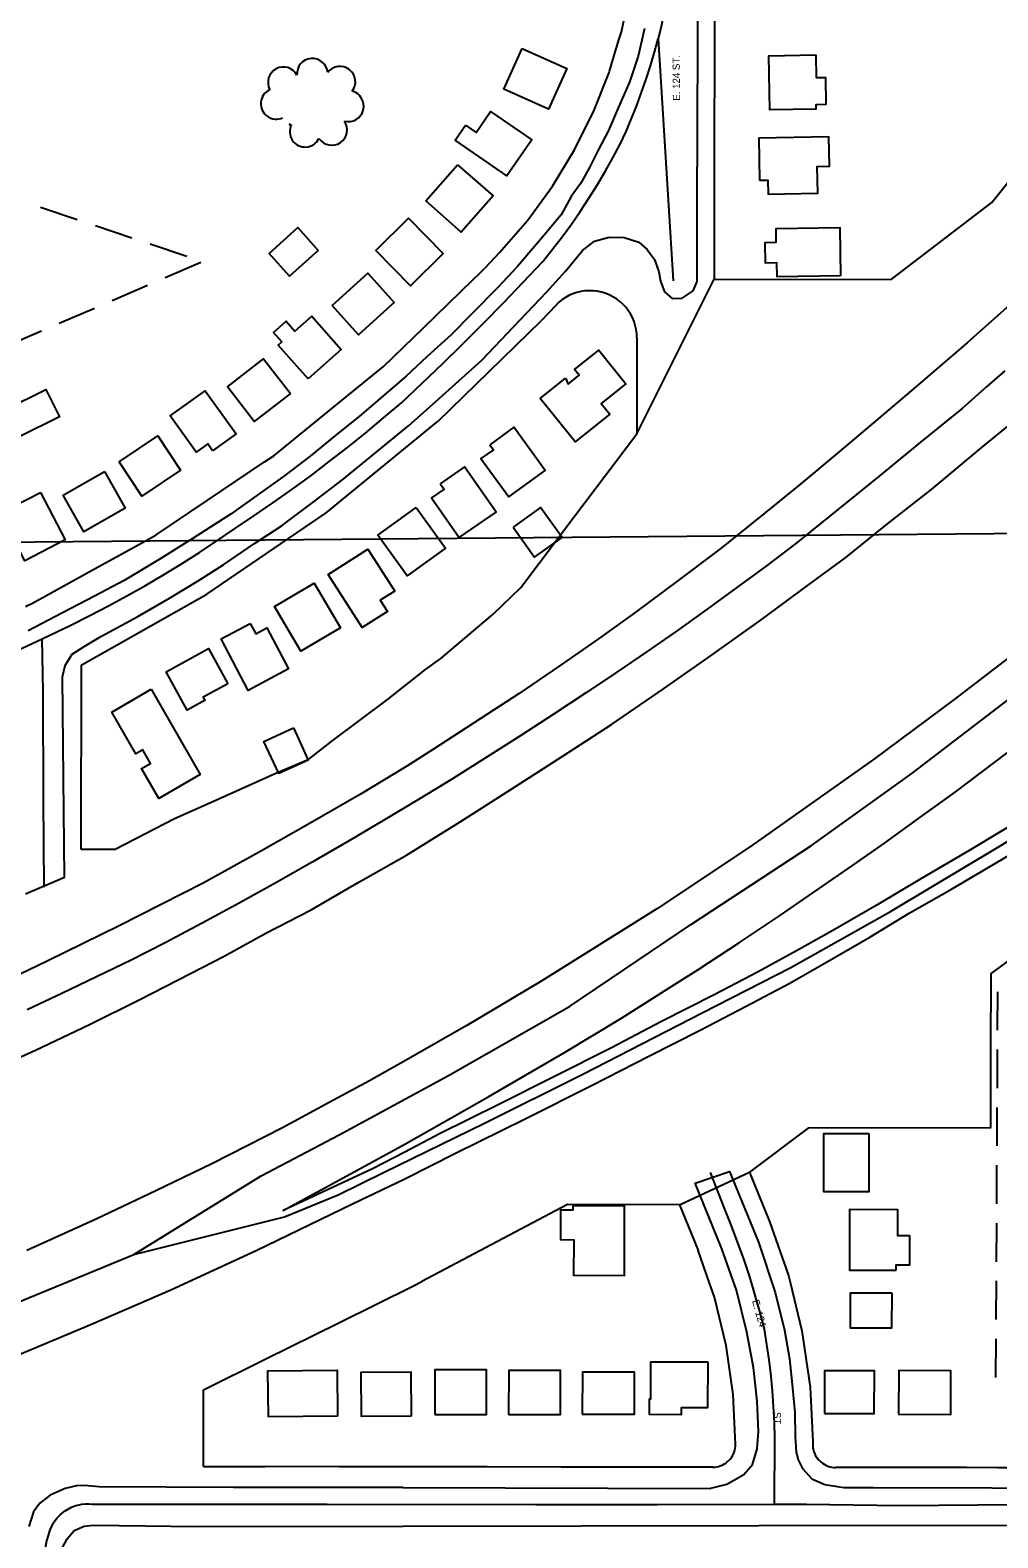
# Model space of a CAD drawing. Extents: x -2233 to 187241, y 4582 to 150524.
# Drawn here: x 112255 to 112882, y 58418 to 59395 of the extents above; entities that cross this region are included whole.
import ezdxf

# ---------------------------------------------------------------- set-up
doc = ezdxf.new("R2010")
doc.units = 0
for name, color, linetype in [('AP_X_Lights', 7, 'Continuous'), ('BLDG', 7, 'Continuous'), ('GE_X_CL_2000', 7, 'Continuous'), ('GRID', 7, 'Continuous'), ('INTERSTATE', 7, 'Continuous'), ('RECREATION', 7, 'Continuous'), ('ROAD', 7, 'Continuous'), ('ROAD-NAME', 7, 'Continuous'), ('RW_X_Fee_RW', 7, 'Continuous'), ('TREES', 7, 'Continuous')]:
    doc.layers.add(name, color=color, linetype=linetype)

msp = doc.modelspace()

# ---------------------------------------------------------------- linework, layer by layer
at = {"layer": 'AP_X_Lights'}
msp.add_line((112661.94, 59389.66), (112671.77, 59232.78), dxfattribs=at)
at = {"layer": 'BLDG'}
for points in [[(112573.74, 59383.4), (112602.84, 59370.37), (112591, 59343.92), (112561.9, 59356.94)], [(112764.24, 59379.14), (112764.47, 59364.52), (112770.44, 59364.62), (112770.73, 59346.95), (112764.22, 59346.85), (112764.26, 59343.96), (112734.41, 59343.47), (112733.83, 59378.64)], [(112537.18, 59333.66), (112543.96, 59328.98), (112553.35, 59342.59), (112580.01, 59324.19), (112563.86, 59300.8), (112530.42, 59323.87)], [(112727.81, 59297.97), (112733.12, 59298.05), (112733.27, 59289), (112765.47, 59289.53), (112765.18, 59306.94), (112773.03, 59307.07), (112772.72, 59325.99), (112727.37, 59325.25)], [(112531.95, 59307.97), (112554.93, 59287.73), (112534.32, 59264.33), (112511.34, 59284.57)], [(112522.68, 59250.55), (112501.36, 59229.56), (112478.88, 59252.4), (112500.19, 59273.38)], [(112441.58, 59252.48), (112422.96, 59235.79), (112409.73, 59250.54), (112428.36, 59267.23)], [(112780.33, 59235.98), (112739.07, 59235.3), (112738.92, 59244.32), (112731.63, 59244.2), (112731.42, 59257.61), (112738.62, 59257.73), (112738.48, 59266.59), (112779.8, 59267.27)], [(112490.83, 59218.62), (112467.62, 59197.83), (112450.61, 59216.84), (112473.82, 59237.62)], [(112434.98, 59169.31), (112415.66, 59191.13), (112417.94, 59193.14), (112412.49, 59199.29), (112420.71, 59206.56), (112426.51, 59200.03), (112437.48, 59209.74), (112456.45, 59188.32)], [(112423.51, 59159.75), (112400.02, 59141.64), (112382.7, 59164.12), (112406.19, 59182.23)], [(112601.84, 59169.59), (112603.76, 59165.85), (112610.83, 59171.51), (112607.79, 59175.32), (112623.44, 59187.85), (112640.94, 59166), (112625.11, 59153.33), (112630.64, 59146.42), (112608.16, 59128.41), (112585.59, 59156.58)], [(112238.79, 59149.35), (112264.96, 59162.32), (112273.73, 59144.62), (112247.58, 59131.64)], [(112373.08, 59122.64), (112369.93, 59127.04), (112362.45, 59121.68), (112345.56, 59145.27), (112368.25, 59161.51), (112388.29, 59133.53)], [(112312.42, 59115.43), (112337.6, 59132.18), (112352.38, 59109.95), (112327.21, 59093.2)], [(112552.8, 59126.54), (112555.16, 59123.3), (112547.12, 59117.48), (112565.1, 59092.65), (112588.71, 59109.74), (112568.39, 59137.82)], [(112520.71, 59101.22), (112523.17, 59097.68), (112515.14, 59092.12), (112533.06, 59066.28), (112556.89, 59082.79), (112536.52, 59112.17)], [(112302.95, 59109.19), (112316.46, 59085.43), (112289.64, 59070.16), (112276.12, 59093.92)], [(112261.56, 59095.62), (112277.48, 59064.81), (112251.27, 59051.26), (112235.34, 59082.07)], [(112505.11, 59085.76), (112524.09, 59059.5), (112499.23, 59041.52), (112480.24, 59067.79)], [(112567.93, 59073), (112581.9, 59053.59), (112599.69, 59066.4), (112585.72, 59085.81)], [(112491.22, 59031.7), (112481.82, 59025.66), (112486.43, 59018.49), (112470.05, 59007.95), (112447.93, 59042.31), (112473.71, 59058.9)], [(112456, 59007.86), (112430.27, 58992.72), (112413.25, 59021.63), (112438.98, 59036.77)], [(112397.51, 59010.72), (112401.12, 59003.92), (112408.31, 59007.73), (112422.41, 58981.15), (112396.25, 58967.28), (112378.55, 59000.67)], [(112382.89, 58971.6), (112367.08, 58962.89), (112368.18, 58960.89), (112356.69, 58954.55), (112343.05, 58979.3), (112370.35, 58994.34)], [(112333.31, 58967.99), (112365.12, 58912.77), (112338.24, 58897.27), (112327.08, 58916.64), (112332.9, 58919.99), (112327.88, 58928.68), (112323.38, 58926.1), (112307.74, 58953.26)], [(112425.47, 58942.99), (112435.08, 58922.12), (112416.01, 58913.33), (112406.4, 58934.2)], [(112798.68, 58680.06), (112798.59, 58642.17), (112769.34, 58642.24), (112769.43, 58680.13)], [(112606.74, 58633.29), (112606.73, 58630.43), (112598.62, 58630.45), (112598.58, 58611.27), (112607.26, 58611.25), (112607.2, 58588.16), (112640.18, 58588.09), (112640.28, 58633.21)], [(112816.37, 58591.42), (112816.39, 58595.05), (112825.19, 58595.04), (112825.23, 58613.65), (112817.39, 58613.67), (112817.43, 58630.67), (112786.12, 58630.74), (112786.03, 58591.5)], [(112813.43, 58576.79), (112813.38, 58553.93), (112786.72, 58553.99), (112786.77, 58576.86)], [(112454.03, 58496.84), (112409.25, 58496.45), (112408.99, 58526.22), (112453.77, 58526.61)], [(112517.2, 58498.01), (112550.7, 58497.93), (112550.77, 58526.8), (112517.26, 58526.88)], [(112565.05, 58497.95), (112598.69, 58497.86), (112598.76, 58526.49), (112565.12, 58526.57)], [(112694.15, 58532.09), (112694.08, 58502.27), (112677.03, 58502.31), (112677.01, 58497.82), (112656.35, 58497.87), (112656.38, 58508.05), (112657.17, 58508.05), (112657.23, 58532.17)], [(112769.86, 58498.58), (112802.15, 58498.51), (112802.22, 58526.25), (112769.93, 58526.33)], [(112817.91, 58498.08), (112851.82, 58498.01), (112851.88, 58526.3), (112817.97, 58526.38)], [(112501.8, 58496.94), (112469.7, 58496.66), (112469.45, 58525.4), (112501.54, 58525.68)], [(112612.79, 58498.18), (112646.6, 58498.11), (112646.66, 58525.3), (112612.85, 58525.38)]]:
    msp.add_lwpolyline(points, close=True, dxfattribs=at)
at = {"layer": 'GE_X_CL_2000'}
for points in [[(112674.75, 59513.68), (112673.38, 59479.04), (112672.72, 59467.46), (112671.83, 59455.9), (112670.73, 59444.36), (112669.4, 59432.84), (112667.86, 59421.35), (112666.1, 59409.89), (112664.12, 59398.47), (112661.94, 59389.66)], [(112322, 58601.64), (112419.7, 58625.98), (112454.58, 58640.34), (112483.87, 58654.7), (112549.39, 58686.78), (112613.25, 58718.64), (112690.58, 58758.24), (112748.04, 58787.66), (112812.69, 58824.06), (112883.1, 58866.13), (112968.12, 58917.71), (113054.39, 58971.65), (113150.57, 59034.21), (113253.76, 59104.14), (113362.87, 59177.68), (113450.77, 59237.58), (113520.19, 59286.04), (113597.75, 59341.18), (113697.89, 59412.19), (113699.46, 59413.32)], [(112262.59, 59000.74), (112281.2, 59009.65), (112293.44, 59015.77), (112305.57, 59022.1), (112317.59, 59028.63), (112329.51, 59035.36), (112341.3, 59042.29), (112352.98, 59049.42), (112364.53, 59056.75), (112375.95, 59064.27), (112387.25, 59071.98), (112399.8, 59080.32), (112412.23, 59088.84), (112424.53, 59097.56), (112436.7, 59106.46), (112448.73, 59115.54), (112460.63, 59124.8), (112472.39, 59134.25), (112484.01, 59143.87), (112495.49, 59153.66), (112508.98, 59166.34), (112522.34, 59179.16), (112535.57, 59192.12), (112548.68, 59205.2), (112561.66, 59218.43), (112574.51, 59231.78), (112587.23, 59245.26), (112593.58, 59253.17), (112599.75, 59261.23), (112605.73, 59269.43), (112611.52, 59277.76), (112617.12, 59286.23), (112622.51, 59294.83), (112627.7, 59303.55), (112632.69, 59312.39), (112637.47, 59321.34), (112641.2, 59329.62), (112644.73, 59337.99), (112648.08, 59346.43), (112651.24, 59354.95), (112654.21, 59363.53), (112656.98, 59372.18), (112659.56, 59380.89), (112661.94, 59389.66)], [(112886.89, 59174.51), (112875.07, 59164.21), (112859.18, 59150.01), (112832.21, 59128.11), (112805.23, 59106.22), (112778.24, 59084.34), (112751.25, 59062.47), (112732.26, 59048.11), (112713.13, 59033.93), (112693.87, 59019.94), (112674.47, 59006.14), (112654.94, 58992.53), (112635.27, 58979.1), (112615.48, 58965.87), (112593.97, 58951.61), (112572.33, 58937.55), (112550.56, 58923.68), (112528.67, 58910.01), (112506.65, 58896.55), (112484.51, 58883.28), (112461.13, 58869.49), (112437.63, 58855.91), (112414, 58842.53), (112390.26, 58829.37), (112366.41, 58816.41), (112342.44, 58803.67), (112320.2, 58792.51), (112297.86, 58781.54), (112275.44, 58770.76), (112252.92, 58760.16)], [(111689.35, 58856.66), (111717.85, 58861.84), (111813.36, 58878.53), (111930.32, 58899.31), (112008.92, 58912.76), (112091.39, 58932.64), (112118.84, 58941.41), (112135.86, 58947.46), (112152.8, 58953.73), (112169.65, 58960.22), (112186.42, 58966.94), (112203.1, 58973.87), (112219.68, 58981.01), (112236.17, 58988.37), (112262.59, 59000.74)], [(112263.92, 58839.7), (112263.46, 58896.5), (112263.3, 58966.44), (112262.59, 59000.74)], [(112322, 58601.64), (112404.65, 58652.72), (112455.09, 58679.29), (112526.13, 58717.6), (112604.53, 58762.37), (112683.68, 58815.8), (112761.41, 58866.74), (112826.6, 58913.46), (112889.1, 58961.39)], [(112695.63, 58654.76), (112705, 58631.03), (112709.4, 58620.19), (112713.56, 58609.25), (112717.48, 58598.22), (112721.14, 58587.11), (112724.56, 58575.93), (112727.73, 58564.67), (112730.65, 58553.34), (112732.34, 58543.35), (112733.78, 58533.33), (112734.8, 58524.82), (112735.94, 58513.19), (112736.66, 58503.1), (112737.14, 58492.99), (112737.37, 58482.87), (112737.31, 58439.82)], [(112186.48, 58545.96), (112322, 58601.64)], [(112269.58, 58427.26), (112272.33, 58431), (112273.94, 58432.68), (112275.69, 58434.21), (112277.56, 58435.58), (112281.63, 58437.81), (112283.8, 58438.65), (112288.31, 58439.74), (112290.62, 58439.99), (112292.94, 58440.04), (112295.26, 58439.88), (112345.06, 58439.79), (112447.33, 58439.8), (112582.73, 58439.67), (112661.55, 58439.69), (112737.31, 58439.82)], [(112737.31, 58439.82), (112758.26, 58439.86), (112818.97, 58438.91), (112894.08, 58439.53), (113038.93, 58438.62), (113119.5, 58438.41), (113160.7, 58439.44), (113241.06, 58439.03), (113306.38, 58438.54), (113333.66, 58438.38)], [(112269.58, 58427.26), (112267.53, 58423.1), (112266.39, 58419.6), (112265.46, 58416.05), (112264.74, 58412.44), (112264.24, 58408.8), (112263.96, 58405.13), (112263.64, 58395.93), (112263.24, 58319.73), (112263.59, 58276.24), (112262.77, 58209.88), (112262.61, 58127.98), (112262.43, 58100.01)]]:
    msp.add_lwpolyline(points, dxfattribs=at)
at = {"layer": 'GRID'}
msp.add_line((114999.62, 59087.27), (109999.81, 59043.63), dxfattribs=at)
at = {"layer": 'INTERSTATE'}
for points in [[(112907.51, 59232.8), (112862.27, 59192.62), (112826.07, 59161.49), (112804.67, 59143.36), (112779.53, 59122.13), (112754.84, 59101.33), (112731.68, 59082.48), (112702.78, 59059.57), (112674.98, 59038.51), (112646.23, 59017.15), (112623.3, 59000.74), (112597.79, 58982.99), (112571.97, 58965.32), (112542.33, 58946.09), (112516.27, 58929.11), (112499.04, 58918.1)], [(112498.75, 58860.45), (112533.71, 58882), (112566.55, 58903.11), (112599.85, 58924.51), (112631.7, 58945.26), (112665.57, 58968.27), (112695.81, 58989.36), (112728.88, 59013.07), (112758.64, 59035.1), (112783.6, 59053.47), (112809.72, 59074.31), (112839.5, 59097.78), (112873.46, 59125.95), (112902.62, 59149.86)], [(112899.26, 58996.17), (112853.92, 58961.28), (112801.6, 58922.4), (112758.95, 58892.18), (112721.84, 58866.05), (112661.22, 58825.69), (112586.49, 58778.97), (112537.95, 58750.16), (112498.1, 58727.36)], [(112497.84, 58673.17), (112552.22, 58704.05), (112601.25, 58732.53), (112638.3, 58754.88), (112668.5, 58774.15), (112687.81, 58786.21), (112714.75, 58803.81), (112740.69, 58821.22), (112765.82, 58838.47), (112788.68, 58854.21), (112808.84, 58868.31), (112833.1, 58886.01), (112854.65, 58901.39), (112888.38, 58926.78)], [(112499.04, 58918.1), (112469.44, 58900.23), (112436.35, 58881.2), (112404.88, 58863.28), (112366.89, 58842.37), (112312.56, 58814.58), (112265.79, 58791.79), (112225.73, 58772.49)], [(112903.33, 58887.36), (112864.15, 58863.63), (112832.34, 58845.19), (112803.36, 58827.88), (112775.32, 58811.55), (112751.82, 58798.51), (112726.75, 58784.8), (112698.75, 58770.21), (112663.65, 58752.45), (112631.68, 58735.57), (112594.33, 58716.84), (112558.74, 58698.84), (112520.19, 58679.88), (112497.81, 58667.94)], [(112497.72, 58650.6), (112530.69, 58667.38), (112575.38, 58689.34), (112619.14, 58711.44), (112656.3, 58730.48), (112689.27, 58747.1), (112719.15, 58762.71), (112746.92, 58777.37), (112771.24, 58791.15), (112799.28, 58807.35), (112824.68, 58822.79), (112852.27, 58838.44), (112881.25, 58855.44), (112912.88, 58874.32)], [(112226.05, 58719.57), (112258.18, 58734.18), (112293.3, 58750.77), (112325.89, 58766.89), (112358.74, 58783.7), (112380.61, 58795.06), (112407.66, 58809.95), (112437, 58825.1), (112467.59, 58842.72), (112498.75, 58860.45)], [(112498.1, 58727.36), (112474.82, 58714.27), (112448.6, 58700.14), (112418.35, 58683.72), (112372.65, 58660.4), (112336.37, 58642.83), (112297.98, 58624.84), (112252.71, 58604.31)], [(112497.81, 58667.94), (112476.72, 58657.27), (112418.91, 58630.17), (112462.52, 58653.9), (112497.84, 58673.17)], [(112246.69, 58536.34), (112294.62, 58556.58), (112346, 58578.85), (112401.37, 58604.35), (112463.91, 58634.48), (112497.72, 58650.6)]]:
    msp.add_lwpolyline(points, dxfattribs=at)
at = {"layer": 'RECREATION'}
for p, q in [((112261.58, 59280.53), (112285.28, 59272.57)), ((112297.13, 59268.59), (112320.83, 59260.64)), ((112332.68, 59256.65), (112356.38, 59248.7)), ((112365.36, 59244.59), (112342.4, 59234.69)), ((112330.92, 59229.74), (112307.97, 59219.84)), ((112296.49, 59214.89), (112273.54, 59204.99)), ((112262.06, 59200.04), (112239.11, 59190.14)), ((112882.14, 58746.99), (112882.26, 58772)), ((112881.95, 58709.49), (112882.07, 58734.49)), ((112881.76, 58672), (112881.88, 58696.99)), ((112881.58, 58634.49), (112881.7, 58659.5)), ((112881.4, 58596.99), (112881.52, 58621.99)), ((112881.2, 58559.5), (112881.33, 58584.49)), ((112881.02, 58522), (112881.14, 58547))]:
    msp.add_line(p, q, dxfattribs=at)
at = {"layer": 'ROAD'}
for points in [[(112500.11, 59138.77), (112517.86, 59154.58), (112547.69, 59181.33), (112572.54, 59207.49), (112589.58, 59225.44), (112601.82, 59239.05), (112612.95, 59252.43), (112620.76, 59258.52), (112630.27, 59260.98), (112639.91, 59260.81), (112649.57, 59257.78), (112654.84, 59253.03), (112659.72, 59246.65), (112662.38, 59238.52), (112663.58, 59232.47), (112666.2, 59225.57), (112671.05, 59221.38), (112677.59, 59221.46), (112684.76, 59226.19), (112687.23, 59232.25), (112687.29, 59279.98), (112687.96, 59440.44), (112687.05, 59496.28)], [(112653.13, 59396.37), (112648.96, 59378.38), (112643.36, 59361.42), (112636.25, 59345.39), (112629.84, 59330.09), (112623.17, 59317.41), (112617.53, 59306.29), (112611.91, 59296.05), (112605.62, 59287.41), (112599.02, 59275.54), (112588.09, 59262.3), (112570.77, 59242.12), (112557.93, 59228.19), (112541.3, 59211.5), (112527.76, 59197.84), (112512.25, 59183.78), (112498.54, 59170.89), (112486.39, 59160.33), (112468.45, 59144.97), (112451.88, 59131.74), (112436.27, 59119.02), (112420.03, 59106.56), (112404.84, 59095.84), (112385.08, 59081.73), (112359.84, 59065.42), (112338.51, 59052.09), (112315.73, 59038.59), (112296.61, 59028.46), (112275.83, 59017.46), (112253.46, 59005.92)], [(112251.69, 58835.37), (112276.97, 58846.29), (112276.03, 58953.39), (112275.84, 58976.08), (112277.55, 58983.41), (112282.11, 58990.74), (112289.85, 58995.75), (112300.55, 59002.22), (112324.53, 59015.13), (112345.25, 59027.07), (112363.76, 59038.36), (112380.41, 59048.98), (112400.35, 59062.4), (112417.46, 59073.83), (112438.31, 59089.39), (112457.44, 59103.96), (112477.67, 59120.42), (112498.04, 59136.94), (112500.11, 59138.77)], [(112496.75, 58450.57), (112695.36, 58450.03), (112706.61, 58452.77), (112717.61, 58459.06), (112723.27, 58465.63), (112726.24, 58475.78), (112726.98, 58486.91), (112726.14, 58506.65), (112723.77, 58528.41), (112719.49, 58551.33), (112712.85, 58578.52), (112703.29, 58605.39), (112686.08, 58647.94), (112708.31, 58655.4), (112727.01, 58609.59), (112737.86, 58577.1), (112744.03, 58552.53), (112747.2, 58534), (112748.77, 58519.65), (112750.53, 58499.33), (112750.83, 58483.58), (112751.41, 58473.61), (112752.81, 58468.48), (112755.64, 58462.9), (112761.57, 58456.26), (112770.16, 58452.63), (112782.51, 58450.73), (112801.56, 58450.6), (113185.45, 58449.62)], [(112496.75, 58450.57), (112386.7, 58450.61), (112299.64, 58451.12), (112292.1, 58451.62), (112285.71, 58451.86), (112277.5, 58449.97), (112267.86, 58445.56), (112261.06, 58440.42), (112256.97, 58434.85), (112254.02, 58425.33)], [(112495.06, 58107.73), (112295.51, 58109.44), (112283.79, 58109.95), (112277.77, 58113.54), (112275.12, 58117.76), (112273.48, 58122.29), (112273.31, 58134.84), (112273.51, 58195.99), (112274.59, 58351.42), (112275.21, 58404.37), (112275.33, 58410.97), (112278.86, 58417.44), (112283.44, 58422.75), (112289.77, 58425.55), (112295.73, 58426.21), (112362.83, 58425.35), (112496.62, 58425.47)], [(112496.62, 58425.47), (112842.72, 58426.13), (113141.4, 58425.35), (113294.22, 58425.62), (113306.3, 58422.73), (113313.33, 58418.51), (113317.46, 58412.71), (113319.98, 58407), (113320.73, 58399.9), (113321.3, 58389.12), (113319.34, 58112.68), (113316.76, 58107.43), (113313.28, 58104.31), (113307.39, 58101.92), (113293.07, 58101.55), (112776.79, 58106.01), (112495.06, 58107.73)]]:
    msp.add_lwpolyline(points, dxfattribs=at)
at = {"layer": 'RW_X_Fee_RW'}
for p, q in [((112813.17, 59233.58), (112878.34, 59283.49)), ((112559.18, 59251.06), (112549.85, 59241.15)), ((112648.15, 59133.63), (112698.27, 59233.74)), ((112698.27, 59233.74), (112813.17, 59233.58)), ((112595.56, 59216.76), (112586.24, 59206.86)), ((112648.23, 59195.82), (112648.15, 59133.63)), ((112608.08, 59080.5), (112648.15, 59133.63)), ((112573.01, 59034.01), (112608.08, 59080.5)), ((112555.02, 59016.65), (112573.01, 59034.01)), ((112521.08, 58987.89), (112555.02, 59016.65)), ((112511.11, 58980.93), (112521.08, 58987.89)), ((112287.93, 58983.71), (112287.76, 58864.4)), ((112486.22, 58961.06), (112511.11, 58980.93)), ((112451.19, 58935.11), (112486.22, 58961.06)), ((112435.55, 58922.7), (112451.19, 58935.11)), ((112414.07, 58913.74), (112435.55, 58922.7)), ((112373.27, 58895.33), (112414.07, 58913.74)), ((112348.47, 58884.19), (112373.27, 58895.33)), ((112309.98, 58864.37), (112348.47, 58884.19)), ((112287.76, 58864.4), (112309.98, 58864.37)), ((112759.6, 58683.66), (112721.29, 58655.09)), ((112877.5, 58683.49), (112759.6, 58683.66)), ((112675.93, 58633.86), (112721.29, 58655.09)), ((112603.13, 58633.96), (112508.8, 58584.05)), ((112675.93, 58633.86), (112603.13, 58633.96)), ((112675.93, 58633.86), (112687.9, 58604.28)), ((112367.25, 58513.94), (112407.28, 58533.75)), ((112367.18, 58464.21), (112367.25, 58513.94)), ((112367.18, 58464.21), (112407.18, 58464.15))]:
    msp.add_line(p, q, dxfattribs=at)
for points in [[(112698.67, 59504.14), (112698.5, 59383.74), (112698.48, 59368.74), (112698.43, 59333.74), (112698.36, 59283.74), (112698.27, 59233.74)], [(112559.18, 59251.06), (112572.69, 59266.64), (112577.21, 59271.86), (112579.62, 59275.16), (112593.43, 59294.09), (112607.73, 59317.6), (112611.76, 59325.69), (112620.01, 59342.23), (112630.18, 59367.8), (112630.47, 59368.74), (112636.59, 59388.88), (112638.18, 59394.13), (112643.94, 59421.03), (112647.43, 59448.33), (112648.63, 59475.82)], [(112878.34, 59283.49), (112918.23, 59333.22), (112958.48, 59383.38)], [(112256.23, 59023.75), (112292.6, 59043.82), (112331.98, 59065.55), (112336.59, 59068.1), (112369.53, 59090.3), (112406.83, 59115.43), (112412.71, 59119.39), (112442.14, 59143.27), (112477.05, 59171.6), (112483.99, 59177.23), (112509.87, 59202.34), (112542.14, 59233.66), (112545.73, 59237.15), (112549.85, 59241.15)], [(112648.23, 59195.82), (112648.12, 59198.51), (112647.77, 59201.19), (112647.18, 59203.82), (112646.36, 59206.38), (112645.32, 59208.87), (112644.07, 59211.25), (112642.6, 59213.52), (112640.95, 59215.64), (112639.11, 59217.61), (112637.11, 59219.41), (112634.95, 59221.03), (112632.66, 59222.45), (112630.25, 59223.66), (112627.75, 59224.66), (112625.17, 59225.43), (112622.53, 59225.97), (112619.85, 59226.27), (112617.16, 59226.34), (112614.47, 59226.17), (112611.8, 59225.76), (112609.19, 59225.12), (112606.64, 59224.25), (112604.17, 59223.15), (112601.82, 59221.85), (112599.58, 59220.34), (112597.49, 59218.64), (112595.56, 59216.76)], [(112287.93, 58983.71), (112369.46, 59029.62), (112446.73, 59082.38), (112518.57, 59141.11), (112519.17, 59141.61), (112586.24, 59206.86)], [(112251.96, 59021.65), (112253.15, 59022.24), (112256.23, 59023.75)], [(112877.64, 58783.49), (112945.75, 58833.4), (113013.86, 58883.3)], [(112877.64, 58783.49), (112877.57, 58733.49), (112877.5, 58683.49)], [(112721.29, 58655.09), (112721.64, 58654.22), (112721.99, 58653.35)], [(112721.99, 58653.35), (112729.94, 58633.7), (112734.25, 58623.03)], [(112734.25, 58623.03), (112746.45, 58588.14), (112747.55, 58583.63), (112755.23, 58552.24), (112760.5, 58515.65), (112762.25, 58480.18)], [(112712.22, 58478.76), (112710.73, 58510.91), (112706.14, 58542.72), (112698.51, 58573.94), (112695.11, 58583.65), (112687.9, 58604.28)], [(112407.28, 58533.75), (112455.31, 58557.53), (112503.34, 58581.31), (112508.8, 58584.05)], [(112697.18, 58463.74), (112698.49, 58463.8), (112699.79, 58463.97), (112701.07, 58464.25), (112702.32, 58464.64), (112703.53, 58465.14), (112704.69, 58465.74), (112705.79, 58466.44), (112706.83, 58467.24), (112707.8, 58468.12), (112708.68, 58469.09), (112709.48, 58470.12), (112710.19, 58471.23), (112710.79, 58472.39), (112711.29, 58473.59), (112711.69, 58474.84), (112711.97, 58476.12), (112712.15, 58477.42), (112712.22, 58478.76)], [(112762.25, 58480.18), (112762.23, 58478.73), (112762.21, 58477.53), (112762.36, 58476.22), (112762.63, 58474.92), (112763.01, 58473.66), (112763.51, 58472.43), (112764.1, 58471.25), (112764.8, 58470.12), (112765.6, 58469.07), (112766.49, 58468.08), (112767.45, 58467.18), (112768.5, 58466.37), (112769.61, 58465.65), (112770.78, 58465.03), (112772, 58464.52), (112773.26, 58464.12), (112774.55, 58463.83), (112775.86, 58463.65), (112777.19, 58463.61)], [(112607.18, 58463.87), (112599.18, 58463.88), (112551.18, 58463.95), (112503.18, 58464.01), (112455.18, 58464.08), (112407.18, 58464.15)], [(112697.18, 58463.74), (112647.18, 58463.81), (112607.18, 58463.87)], [(112882.19, 58463.48), (112862.19, 58463.51), (112812.19, 58463.58), (112777.19, 58463.61)], [(113038.27, 58463.27), (113000.88, 58463.43), (112999.58, 58463.35), (112998.27, 58463.32), (112962.19, 58463.37), (112912.19, 58463.44), (112882.19, 58463.48)]]:
    msp.add_lwpolyline(points, dxfattribs=at)
at = {"layer": 'TREES'}
for centre, radius, start, end in [((112437.77, 59366.91), 10, 4.87346, 184.87346), ((112418.99, 59361.34), 10, 28.15796, 208.15796), ((112455.69, 59361.7), 10, 322.68274, 142.68274), ((112414.35, 59347.53), 10, 114.65899, 294.65899), ((112461.1, 59345.96), 10, 255.28677, 75.28677), ((112423.62, 59334.4), 0.741, 145.15599, 325.15599), ((112433.16, 59329.47), 10, 153.20875, 333.20875), ((112450.32, 59330.62), 10, 214.50825, 34.50825)]:
    msp.add_arc(centre, radius, start, end, dxfattribs=at)

# ---------------------------------------------------------------- texts
at = {"layer": 'ROAD-NAME'}
for s, rotation, p in [('E. 124 ST.', 90.5, (112676.23, 59349.54)), ('E. 124', 285.65982, (112722.85, 58571.59)), ('ST.', 271.80248, (112736.84, 58499.5))]:
    msp.add_text(s, height=4.68, rotation=rotation, dxfattribs=at).set_placement(p)

doc.saveas('drawing.dxf')
